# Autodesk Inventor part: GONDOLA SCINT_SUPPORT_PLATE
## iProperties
Shininess: 64.0
Length Units: 11272
Angle Units: 11279
Time Units: 11290
Mass Units: 11286
Length Display Precision: 3
Angle Display Precision: 2
Compacted: True
Part Number: GONDOLA SCINT_SUPPORT_PLATE
Document SubType Name: Modeling
Created: 2004-08
Designer: John Blackburn
Manufacturer: Standard
Standards Organization: Custom
Material: PVC-Piping
Density: 0.0
Volumn: 0.0
Area: 0.0
PropertySet Name: Model Information
Control State: 0
Master: False
Checked Out: False
Author: John Blackburn
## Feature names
1. ExtrusionMidplane1
2. AM_HOLE_SI0017_1 [Hole]
